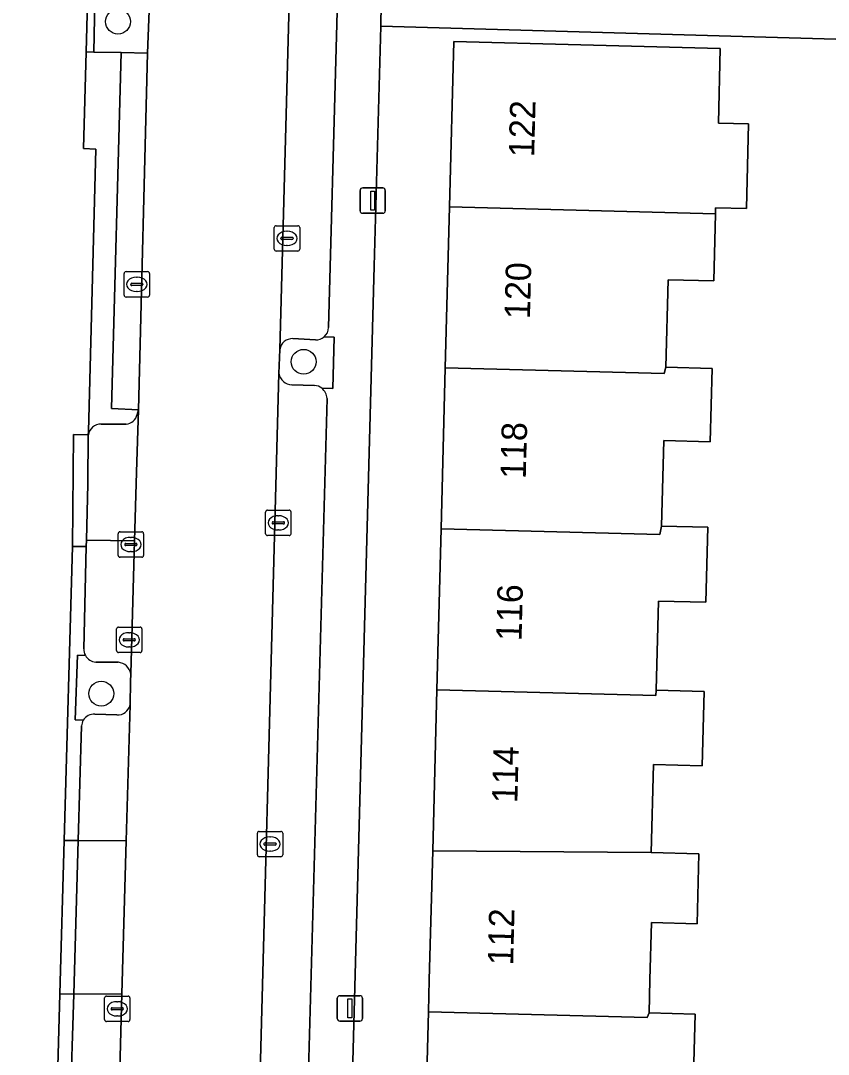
# Model space of a CAD drawing. Extents: x 162082 to 163401, y 388089 to 388636.
# Drawn here: x 162324.72 to 162356.5, y 388247.07 to 388287.72 of the extents above; entities that cross this region are included whole.
import ezdxf

# ---------------------------------------------------------------- set-up
doc = ezdxf.new("R2010")
doc.units = 0
for name, color, linetype in [('IMGEO_Berm_open', 7, 'Continuous'), ('IMGEO_Boom', 7, 'Continuous'), ('IMGEO_Erf', 7, 'Continuous'), ('IMGEO_Fietspad_gesloten', 7, 'Continuous'), ('IMGEO_Groenvoorziening', 7, 'Continuous'), ('IMGEO_Kolk', 7, 'Continuous'), ('IMGEO_Lichtmast', 7, 'Continuous'), ('IMGEO_Pand', 7, 'Continuous'), ('IMGEO_Pand_nummerreeks', 7, 'Continuous'), ('IMGEO_Parkeervlak_open', 7, 'Continuous'), ('IMGEO_Rijbaan_lokaal_gesloten', 7, 'Continuous'), ('IMGEO_Rijbaan_lokaal_open', 7, 'Continuous'), ('IMGEO_Rioolput', 7, 'Continuous'), ('IMGEO_Voetpad_open', 7, 'Continuous')]:
    doc.layers.add(name, color=color, linetype=linetype)

msp = doc.modelspace()

# ---------------------------------------------------------------- linework, layer by layer
at = {"layer": 'IMGEO_Berm_open'}
for points in [[(162327.895, 388289.495), (162328.369, 388307.541), (162327.861, 388307.546), (162327.288, 388286.498), (162327.596, 388286.49), (162327.652, 388289.17), (162327.984, 388289.163)], [(162327.297, 388267.04), (162326.752, 388267.046), (162326.43, 388255.479), (162326.974, 388255.482), (162327.113, 388259.985)], [(162327.198, 388263.017), (162327.297, 388267.04)], [(162327.181, 388260.211), (162326.866, 388260.221), (162326.947, 388262.772), (162327.262, 388262.762)], [(162326.664, 388244.93), (162326.803, 388249.442), (162326.263, 388249.445), (162325.933, 388237.577), (162326.46, 388237.576), (162326.594, 388242.059)]]:
    msp.add_lwpolyline(points, dxfattribs=at)
for centre, radius, start, end in [((162327.726, 388263.014), 0.528, 179.6824, 208.4958), ((162327.598, 388259.962), 0.486, 149.1875, 177.321)]:
    msp.add_arc(centre, radius, start, end, dxfattribs=at)
at = {"layer": 'IMGEO_Boom'}
for centre in [(162328.546, 388287.687), (162335.851, 388274.307), (162327.888, 388261.256)]:
    msp.add_circle(centre, 0.489, dxfattribs=at)
at = {"layer": 'IMGEO_Erf'}
for points in [[(162360.923, 388286.882), (162338.884, 388287.51), (162338.626, 388278.073), (162337.426, 388233.104)], [(162340.599, 388242.417), (162340.764, 388248.748), (162340.797, 388250), (162340.929, 388255.078), (162341.094, 388261.41), (162341.258, 388267.74), (162341.423, 388274.07), (162341.588, 388280.402), (162341.757, 388286.908), (162346.756, 388286.778), (162352.246, 388286.635), (162352.17, 388283.695), (162353.36, 388283.664), (162353.274, 388280.337), (162352.063, 388280.368), (162352.057, 388280.13), (162351.988, 388277.49), (162350.193, 388277.536), (162350.104, 388274.093), (162351.927, 388274.045), (162351.852, 388271.162), (162350.02, 388271.21), (162349.933, 388267.846), (162351.756, 388267.799), (162351.679, 388264.85), (162349.809, 388264.898), (162349.718, 388261.391), (162351.607, 388261.342), (162351.532, 388258.424), (162349.616, 388258.474), (162349.526, 388255.01), (162351.403, 388254.961), (162351.332, 388252.208), (162349.536, 388252.254), (162349.478, 388250), (162349.444, 388248.702), (162351.259, 388248.655), (162351.184, 388245.796)]]:
    msp.add_lwpolyline(points, dxfattribs=at)
at = {"layer": 'IMGEO_Fietspad_gesloten'}
msp.add_lwpolyline([(162324.717, 388195.314), (162324.9, 388201.505), (162325.254, 388213.522), (162325.431, 388219.544), (162325.433, 388219.603), (162325.765, 388231.539), (162325.933, 388237.577), (162326.263, 388249.445), (162326.43, 388255.479), (162326.752, 388267.046), (162326.802, 388271.444), (162327.379, 388271.429), (162327.38, 388271.563), (162327.677, 388282.671), (162327.185, 388282.695), (162327.288, 388286.498), (162327.861, 388307.546), (162327.998, 388312.547), (162328.302, 388323.735), (162328.466, 388329.762)], dxfattribs=at)
at = {"layer": 'IMGEO_Groenvoorziening'}
for points in [[(162327.984, 388289.163), (162327.652, 388289.17), (162327.596, 388286.49), (162328.675, 388286.47), (162329.71, 388286.451), (162329.78, 388288.456), (162329.772, 388288.568)], [(162336.321, 388275.169), (162335.426, 388275.218)], [(162336.565, 388273.265), (162337, 388273.254), (162337.05, 388275.282)], [(162337.05, 388275.282), (162336.658, 388275.292)], [(162334.914, 388274.789), (162334.879, 388273.842)], [(162335.387, 388273.403), (162336.282, 388273.381)], [(162327.262, 388262.762), (162326.947, 388262.772), (162326.866, 388260.221), (162327.181, 388260.211)], [(162328.56, 388262.489), (162327.669, 388262.493)], [(162329.021, 388260.81), (162329.041, 388261.739), (162329.048, 388262.041)], [(162327.635, 388260.446), (162328.502, 388260.419)]]:
    msp.add_lwpolyline(points, dxfattribs=at)
for centre, radius, start, end in [((162335.407, 388274.721), 0.497, 87.7586, 172.16), ((162336.331, 388275.665), 0.497, 268.873, 311.2297), ((162335.414, 388273.948), 0.545, 191.1771, 267.1575), ((162336.224, 388272.835), 0.549, 51.5372, 83.8859), ((162327.723, 388263.017), 0.527, 208.9529, 264.1229), ((162328.512, 388261.947), 0.545, 9.9831, 84.911), ((162327.597, 388259.964), 0.484, 85.4528, 149.2813), ((162328.533, 388260.918), 0.5, 266.4198, 347.5669)]:
    msp.add_arc(centre, radius, start, end, dxfattribs=at)
at = {"layer": 'IMGEO_Kolk'}
for p, q in [((162334.696, 388278.734), (162334.696, 388279.586)), ((162334.771, 388279.66), (162335.623, 388279.66)), ((162335.697, 388279.586), (162335.697, 388278.734)), ((162334.955, 388279.154), (162334.955, 388279.166)), ((162334.998, 388279.203), (162335.396, 388279.203)), ((162335.184, 388279.44), (162335.209, 388279.44)), ((162335.439, 388279.166), (162335.439, 388279.154)), ((162335.393, 388279.117), (162334.995, 388279.117)), ((162335.207, 388278.88), (162335.182, 388278.88)), ((162335.623, 388278.66), (162334.771, 388278.66)), ((162334.353, 388267.548), (162334.353, 388268.4)), ((162334.428, 388268.474), (162335.28, 388268.474)), ((162334.841, 388268.254), (162334.866, 388268.254)), ((162335.354, 388268.4), (162335.354, 388267.548)), ((162334.612, 388267.968), (162334.612, 388267.98)), ((162335.05, 388267.931), (162334.652, 388267.931)), ((162334.655, 388268.017), (162335.053, 388268.017)), ((162335.096, 388267.98), (162335.096, 388267.968)), ((162328.553, 388266.696), (162328.553, 388267.548)), ((162328.628, 388267.622), (162329.48, 388267.622)), ((162329.041, 388267.402), (162329.066, 388267.402)), ((162329.554, 388267.548), (162329.554, 388266.696)), ((162335.28, 388267.474), (162334.428, 388267.474)), ((162334.864, 388267.694), (162334.839, 388267.694)), ((162328.812, 388267.116), (162328.812, 388267.128)), ((162329.25, 388267.079), (162328.852, 388267.079)), ((162328.855, 388267.165), (162329.253, 388267.165)), ((162329.296, 388267.128), (162329.296, 388267.116)), ((162329.48, 388266.622), (162328.628, 388266.622)), ((162329.064, 388266.842), (162329.039, 388266.842)), ((162334.031, 388254.914), (162334.031, 388255.766)), ((162334.106, 388255.84), (162334.958, 388255.84)), ((162334.519, 388255.62), (162334.544, 388255.62)), ((162335.032, 388255.766), (162335.032, 388254.914)), ((162334.29, 388255.334), (162334.29, 388255.346)), ((162334.728, 388255.297), (162334.33, 388255.297)), ((162334.333, 388255.383), (162334.731, 388255.383)), ((162334.774, 388255.346), (162334.774, 388255.334)), ((162334.958, 388254.84), (162334.106, 388254.84)), ((162334.542, 388255.06), (162334.517, 388255.06)), ((162328.016, 388248.435), (162328.016, 388249.287)), ((162328.091, 388249.361), (162328.943, 388249.361)), ((162328.504, 388249.141), (162328.529, 388249.141)), ((162329.017, 388249.287), (162329.017, 388248.435)), ((162328.275, 388248.855), (162328.275, 388248.867)), ((162328.713, 388248.818), (162328.315, 388248.818)), ((162328.318, 388248.904), (162328.716, 388248.904)), ((162328.759, 388248.867), (162328.759, 388248.855)), ((162328.943, 388248.361), (162328.091, 388248.361)), ((162328.527, 388248.581), (162328.502, 388248.581))]:
    msp.add_line(p, q, dxfattribs=at)
for points in [[(162334.696, 388278.734), (162334.696, 388279.586)], [(162334.771, 388279.66), (162335.623, 388279.66)], [(162335.697, 388279.586), (162335.697, 388278.734)], [(162335.623, 388278.66), (162334.771, 388278.66)], [(162334.353, 388267.548), (162334.353, 388268.4)], [(162334.428, 388268.474), (162335.28, 388268.474)], [(162335.354, 388268.4), (162335.354, 388267.548)], [(162328.553, 388266.696), (162328.553, 388267.548)], [(162328.628, 388267.622), (162329.48, 388267.622)], [(162329.554, 388267.548), (162329.554, 388266.696)], [(162335.28, 388267.474), (162334.428, 388267.474)], [(162329.48, 388266.622), (162328.628, 388266.622)], [(162334.031, 388254.914), (162334.031, 388255.766)], [(162334.106, 388255.84), (162334.958, 388255.84)], [(162335.032, 388255.766), (162335.032, 388254.914)], [(162334.958, 388254.84), (162334.106, 388254.84)], [(162328.016, 388248.435), (162328.016, 388249.287)], [(162328.091, 388249.361), (162328.943, 388249.361)], [(162329.017, 388249.287), (162329.017, 388248.435)], [(162328.943, 388248.361), (162328.091, 388248.361)]]:
    msp.add_lwpolyline(points, dxfattribs=at)
for centre, radius, start, end in [((162334.773, 388279.584), 0.0765, 91.552, 178.448), ((162334.773, 388279.584), 0.0765, 91.552, 178.448), ((162335.621, 388279.584), 0.0765, 1.552, 88.448), ((162335.621, 388279.584), 0.0765, 1.552, 88.448), ((162334.995, 388279.163), 0.0403, 85.8775, 175.7526), ((162334.992, 388279.153), 0.0366, 178.938, 274.7102), ((162335.396, 388279.16), 0.043, 264.8664, 352.4533), ((162335.4, 388279.165), 0.0386, 1.7309, 96.639), ((162334.773, 388278.736), 0.0765, 181.552, 268.448), ((162334.773, 388278.736), 0.0765, 181.552, 268.448), ((162335.621, 388278.736), 0.0765, 271.552, 358.448), ((162335.621, 388278.736), 0.0765, 271.552, 358.448), ((162334.43, 388268.398), 0.0765, 91.552, 178.448), ((162334.43, 388268.398), 0.0765, 91.552, 178.448), ((162335.278, 388268.398), 0.0765, 1.552, 88.448), ((162335.278, 388268.398), 0.0765, 1.552, 88.448), ((162334.652, 388267.977), 0.0403, 85.8775, 175.7526), ((162334.649, 388267.967), 0.0366, 178.938, 274.7102), ((162335.053, 388267.974), 0.043, 264.8664, 352.4533), ((162335.057, 388267.979), 0.0386, 1.7309, 96.639), ((162328.63, 388267.546), 0.0765, 91.552, 178.448), ((162328.63, 388267.546), 0.0765, 91.552, 178.448), ((162329.478, 388267.546), 0.0765, 1.552, 88.448), ((162329.478, 388267.546), 0.0765, 1.552, 88.448), ((162334.43, 388267.55), 0.0765, 181.552, 268.448), ((162334.43, 388267.55), 0.0765, 181.552, 268.448), ((162335.278, 388267.55), 0.0765, 271.552, 358.448), ((162335.278, 388267.55), 0.0765, 271.552, 358.448), ((162328.852, 388267.125), 0.0403, 85.8775, 175.7526), ((162328.849, 388267.115), 0.0366, 178.938, 274.7102), ((162329.253, 388267.122), 0.043, 264.8664, 352.4533), ((162329.257, 388267.127), 0.0386, 1.7309, 96.639), ((162328.63, 388266.698), 0.0765, 181.552, 268.448), ((162328.63, 388266.698), 0.0765, 181.552, 268.448), ((162329.478, 388266.698), 0.0765, 271.552, 358.448), ((162329.478, 388266.698), 0.0765, 271.552, 358.448), ((162334.108, 388255.764), 0.0765, 91.552, 178.448), ((162334.108, 388255.764), 0.0765, 91.552, 178.448), ((162334.956, 388255.764), 0.0765, 1.552, 88.448), ((162334.956, 388255.764), 0.0765, 1.552, 88.448), ((162334.33, 388255.343), 0.0403, 85.8775, 175.7526), ((162334.327, 388255.333), 0.0366, 178.938, 274.7102), ((162334.731, 388255.34), 0.043, 264.8664, 352.4533), ((162334.735, 388255.345), 0.0386, 1.7309, 96.639), ((162334.108, 388254.916), 0.0765, 181.552, 268.448), ((162334.108, 388254.916), 0.0765, 181.552, 268.448), ((162334.956, 388254.916), 0.0765, 271.552, 358.448), ((162334.956, 388254.916), 0.0765, 271.552, 358.448), ((162328.093, 388249.285), 0.0765, 91.552, 178.448), ((162328.093, 388249.285), 0.0765, 91.552, 178.448), ((162328.941, 388249.285), 0.0765, 1.552, 88.448), ((162328.941, 388249.285), 0.0765, 1.552, 88.448), ((162328.315, 388248.864), 0.0403, 85.8775, 175.7526), ((162328.312, 388248.854), 0.0366, 178.938, 274.7102), ((162328.716, 388248.861), 0.043, 264.8664, 352.4533), ((162328.72, 388248.866), 0.0386, 1.7309, 96.639), ((162328.093, 388248.437), 0.0765, 181.552, 268.448), ((162328.093, 388248.437), 0.0765, 181.552, 268.448), ((162328.941, 388248.437), 0.0765, 271.552, 358.448), ((162328.941, 388248.437), 0.0765, 271.552, 358.448)]:
    msp.add_arc(centre, radius, start, end, dxfattribs=at)
for centre, major_axis, ratio, start_param, end_param in [((162335.183, 388279.16), (-0.387, 0.002), 0.722429, 4.712389, 7.853982), ((162335.208, 388279.16), (-0.39, 0.002), 0.717154, 1.570796, 4.712389), ((162334.84, 388267.974), (-0.387, 0.002), 0.722429, 4.712389, 7.853982), ((162334.865, 388267.974), (-0.39, 0.002), 0.717154, 1.570796, 4.712389), ((162329.04, 388267.122), (-0.387, 0.002), 0.722429, 4.712389, 7.853982), ((162329.065, 388267.122), (-0.39, 0.002), 0.717154, 1.570796, 4.712389), ((162334.518, 388255.34), (-0.387, 0.002), 0.722429, 4.712389, 7.853982), ((162334.543, 388255.34), (-0.39, 0.002), 0.717154, 1.570796, 4.712389), ((162328.503, 388248.861), (-0.387, 0.002), 0.722429, 4.712389, 7.853982), ((162328.528, 388248.861), (-0.39, 0.002), 0.717154, 1.570796, 4.712389)]:
    msp.add_ellipse(centre, major_axis=major_axis, ratio=ratio, start_param=start_param, end_param=end_param, dxfattribs=at)
at = {"layer": 'IMGEO_Lichtmast'}
for p, q in [((162338.074, 388280.248), (162338.074, 388281.048)), ((162338.074, 388281.048), (162338.074, 388280.248)), ((162338.174, 388281.148), (162338.964, 388281.148)), ((162338.964, 388281.148), (162338.174, 388281.148)), ((162339.064, 388281.048), (162339.064, 388280.248)), ((162339.064, 388280.248), (162339.064, 388281.048)), ((162338.964, 388280.148), (162338.174, 388280.148)), ((162338.174, 388280.148), (162338.964, 388280.148)), ((162337.175, 388248.476), (162337.175, 388249.276)), ((162337.175, 388249.276), (162337.175, 388248.476)), ((162337.275, 388249.376), (162338.065, 388249.376)), ((162338.065, 388249.376), (162337.275, 388249.376)), ((162338.165, 388249.276), (162338.165, 388248.476)), ((162338.165, 388248.476), (162338.165, 388249.276)), ((162338.065, 388248.376), (162337.275, 388248.376)), ((162337.275, 388248.376), (162338.065, 388248.376))]:
    msp.add_line(p, q, dxfattribs=at)
for points in [[(162338.494, 388281.023), (162338.644, 388281.023), (162338.644, 388280.273), (162338.494, 388280.273), (162338.494, 388281.023)], [(162337.595, 388249.251), (162337.745, 388249.251), (162337.745, 388248.501), (162337.595, 388248.501), (162337.595, 388249.251)]]:
    msp.add_lwpolyline(points, dxfattribs=at)
for centre, start, end in [((162338.174, 388281.048), 90, 180), ((162338.174, 388281.048), 90, 180), ((162338.964, 388281.048), 0, 90), ((162338.964, 388281.048), 360, 90), ((162338.174, 388280.248), 180, 270), ((162338.174, 388280.248), 180, 270), ((162338.964, 388280.248), 270, 0), ((162338.964, 388280.248), 270, 0), ((162337.275, 388249.276), 90, 180), ((162337.275, 388249.276), 90, 180), ((162338.065, 388249.276), 0, 90), ((162338.065, 388249.276), 360, 90), ((162337.275, 388248.476), 180, 270), ((162337.275, 388248.476), 180, 270), ((162338.065, 388248.476), 270, 0), ((162338.065, 388248.476), 270, 0)]:
    msp.add_arc(centre, 0.1, start, end, dxfattribs=at)
at = {"layer": 'IMGEO_Pand'}
for points in [[(162341.588, 388280.402), (162352.057, 388280.13), (162352.063, 388280.368), (162353.274, 388280.337), (162353.36, 388283.664), (162352.17, 388283.695), (162352.246, 388286.635), (162346.756, 388286.778), (162341.757, 388286.908)], [(162341.423, 388274.07), (162350.033, 388273.847), (162350.104, 388274.093), (162350.193, 388277.536), (162351.988, 388277.49), (162352.057, 388280.13), (162341.588, 388280.402)], [(162341.423, 388274.07), (162341.258, 388267.74), (162349.868, 388267.517), (162349.933, 388267.846), (162350.02, 388271.21), (162351.852, 388271.162), (162351.927, 388274.045), (162350.104, 388274.093), (162350.033, 388273.847)], [(162349.718, 388261.391), (162349.809, 388264.898), (162351.679, 388264.85), (162351.756, 388267.799), (162349.933, 388267.846), (162349.868, 388267.517), (162341.258, 388267.74), (162341.094, 388261.41), (162349.704, 388261.187)], [(162349.718, 388261.391), (162349.704, 388261.187), (162341.094, 388261.41), (162340.929, 388255.078), (162349.526, 388255.01), (162349.616, 388258.474), (162351.532, 388258.424), (162351.607, 388261.342)], [(162349.444, 388248.702), (162349.478, 388250), (162349.536, 388252.254), (162351.332, 388252.208), (162351.403, 388254.961), (162349.526, 388255.01), (162340.929, 388255.078), (162340.797, 388250), (162340.764, 388248.748), (162349.373, 388248.524)], [(162340.599, 388242.417), (162349.209, 388242.193), (162349.267, 388242.371), (162349.358, 388245.844), (162351.184, 388245.796), (162351.259, 388248.655), (162349.444, 388248.702), (162349.373, 388248.524), (162340.764, 388248.748)]]:
    msp.add_lwpolyline(points, close=True, dxfattribs=at)
at = {"layer": 'IMGEO_Parkeervlak_open'}
for points in [[(162335.561, 388298.654), (162334.914, 388274.789)], [(162336.831, 388275.651), (162337.429, 388297.641)], [(162335.426, 388275.218), (162336.321, 388275.169)], [(162334.879, 388273.842), (162333.941, 388238.998)], [(162336.282, 388273.381), (162335.387, 388273.403)], [(162335.858, 388239.827), (162336.775, 388272.868)], [(162329.198, 388267.26), (162327.303, 388267.291), (162327.297, 388267.04), (162327.198, 388263.017)], [(162329.048, 388262.041), (162329.198, 388267.26)], [(162327.669, 388262.493), (162328.56, 388262.489)], [(162327.113, 388259.985), (162326.974, 388255.482), (162328.872, 388255.468), (162329.021, 388260.81)], [(162328.502, 388260.419), (162327.635, 388260.446)], [(162328.704, 388249.449), (162326.803, 388249.442), (162326.664, 388244.93)], [(162328.552, 388243.983), (162328.704, 388249.449)]]:
    msp.add_lwpolyline(points, dxfattribs=at)
for centre, radius, start, end in [((162336.366, 388275.654), 0.465, 308.897, 359.6447), ((162335.407, 388274.721), 0.497, 87.7586, 172.16), ((162336.331, 388275.665), 0.497, 268.873, 311.2297), ((162335.414, 388273.948), 0.545, 191.1771, 267.1575), ((162336.224, 388272.835), 0.549, 51.5372, 83.8859), ((162336.22, 388272.829), 0.556, 4.0585, 51.6962), ((162327.726, 388263.014), 0.528, 179.6824, 208.4958), ((162327.723, 388263.017), 0.527, 208.9529, 264.1229), ((162328.512, 388261.947), 0.545, 9.9831, 84.911), ((162327.597, 388259.964), 0.484, 85.4528, 149.2813), ((162328.533, 388260.918), 0.5, 266.4198, 347.5669), ((162327.598, 388259.962), 0.486, 149.1875, 177.321)]:
    msp.add_arc(centre, radius, start, end, dxfattribs=at)
at = {"layer": 'IMGEO_Rijbaan_lokaal_gesloten'}
for points in [[(162333.941, 388238.998), (162334.879, 388273.842), (162334.914, 388274.789), (162335.561, 388298.654), (162335.603, 388299.877), (162336.258, 388323.727), (162336.315, 388326.293), (162336.353, 388327.986), (162337.184, 388357.359)], [(162330.881, 388329.508), (162330.725, 388323.684), (162330.58, 388318.269), (162330.569, 388317.993), (162330.545, 388317.428), (162330.4, 388312.003), (162330.292, 388307.974), (162329.772, 388288.568), (162329.78, 388288.456), (162329.71, 388286.451), (162329.348, 388272.419), (162329.276, 388269.966), (162329.198, 388267.26), (162329.048, 388262.041), (162329.041, 388261.739), (162329.021, 388260.81), (162328.872, 388255.468), (162328.704, 388249.449), (162328.552, 388243.983)]]:
    msp.add_lwpolyline(points, dxfattribs=at)
at = {"layer": 'IMGEO_Rijbaan_lokaal_open'}
for points in [[(162329.276, 388269.966), (162329.348, 388272.419), (162329.299, 388272.239)], [(162328.866, 388271.851), (162327.881, 388271.855)], [(162327.379, 388271.429), (162327.359, 388269.532), (162327.358, 388269.504), (162327.303, 388267.291), (162329.198, 388267.26), (162329.276, 388269.966)]]:
    msp.add_lwpolyline(points, dxfattribs=at)
for points in [[(162327.358, 388269.504), (162327.359, 388269.532), (162327.379, 388271.429), (162326.802, 388271.444), (162326.752, 388267.046), (162327.297, 388267.04), (162327.303, 388267.291)], [(162326.974, 388255.482), (162326.43, 388255.479), (162326.263, 388249.445), (162326.803, 388249.442)], [(162328.872, 388255.468), (162326.974, 388255.482), (162326.803, 388249.442), (162328.704, 388249.449)]]:
    msp.add_lwpolyline(points, close=True, dxfattribs=at)
for centre, radius, start, end in [((162328.819, 388272.339), 0.49, 275.4583, 348.267), ((162327.862, 388271.369), 0.486, 87.7081, 172.9281)]:
    msp.add_arc(centre, radius, start, end, dxfattribs=at)
at = {"layer": 'IMGEO_Rioolput'}
for p, q in [((162328.787, 388276.928), (162328.787, 388277.78)), ((162328.862, 388277.854), (162329.714, 388277.854)), ((162329.275, 388277.634), (162329.3, 388277.634)), ((162329.788, 388277.78), (162329.788, 388276.928)), ((162329.046, 388277.348), (162329.046, 388277.36)), ((162329.484, 388277.311), (162329.086, 388277.311)), ((162329.089, 388277.397), (162329.487, 388277.397)), ((162329.53, 388277.36), (162329.53, 388277.348)), ((162329.714, 388276.854), (162328.862, 388276.854)), ((162329.298, 388277.074), (162329.273, 388277.074)), ((162328.488, 388262.947), (162328.488, 388263.799)), ((162328.563, 388263.873), (162329.415, 388263.873)), ((162329.489, 388263.799), (162329.489, 388262.947)), ((162328.747, 388263.367), (162328.747, 388263.379)), ((162329.185, 388263.33), (162328.787, 388263.33)), ((162328.79, 388263.416), (162329.188, 388263.416)), ((162328.976, 388263.653), (162329.001, 388263.653)), ((162329.231, 388263.379), (162329.231, 388263.367)), ((162329.415, 388262.873), (162328.563, 388262.873)), ((162328.999, 388263.093), (162328.974, 388263.093))]:
    msp.add_line(p, q, dxfattribs=at)
for points in [[(162328.787, 388276.928), (162328.787, 388277.78)], [(162328.862, 388277.854), (162329.714, 388277.854)], [(162329.788, 388277.78), (162329.788, 388276.928)], [(162329.714, 388276.854), (162328.862, 388276.854)], [(162328.488, 388262.947), (162328.488, 388263.799)], [(162328.563, 388263.873), (162329.415, 388263.873)], [(162329.489, 388263.799), (162329.489, 388262.947)], [(162329.415, 388262.873), (162328.563, 388262.873)]]:
    msp.add_lwpolyline(points, dxfattribs=at)
for centre, radius, start, end in [((162328.864, 388277.778), 0.0765, 91.552, 178.448), ((162328.864, 388277.778), 0.0765, 91.552, 178.448), ((162329.712, 388277.778), 0.0765, 1.552, 88.448), ((162329.712, 388277.778), 0.0765, 1.552, 88.448), ((162329.086, 388277.357), 0.0403, 85.8775, 175.7526), ((162329.083, 388277.347), 0.0366, 178.938, 274.7102), ((162329.487, 388277.354), 0.043, 264.8664, 352.4533), ((162329.491, 388277.359), 0.0386, 1.7309, 96.639), ((162328.864, 388276.93), 0.0765, 181.552, 268.448), ((162328.864, 388276.93), 0.0765, 181.552, 268.448), ((162329.712, 388276.93), 0.0765, 271.552, 358.448), ((162329.712, 388276.93), 0.0765, 271.552, 358.448), ((162328.565, 388263.797), 0.0765, 91.552, 178.448), ((162328.565, 388263.797), 0.0765, 91.552, 178.448), ((162329.413, 388263.797), 0.0765, 1.552, 88.448), ((162329.413, 388263.797), 0.0765, 1.552, 88.448), ((162328.787, 388263.376), 0.0403, 85.8775, 175.7526), ((162328.784, 388263.366), 0.0366, 178.938, 274.7102), ((162329.188, 388263.373), 0.043, 264.8664, 352.4533), ((162329.192, 388263.378), 0.0386, 1.7309, 96.639), ((162328.565, 388262.949), 0.0765, 181.552, 268.448), ((162328.565, 388262.949), 0.0765, 181.552, 268.448), ((162329.413, 388262.949), 0.0765, 271.552, 358.448), ((162329.413, 388262.949), 0.0765, 271.552, 358.448)]:
    msp.add_arc(centre, radius, start, end, dxfattribs=at)
for centre, major_axis, ratio, start_param, end_param in [((162329.274, 388277.354), (-0.387, 0.002), 0.722429, 4.712389, 7.853982), ((162329.299, 388277.354), (-0.39, 0.002), 0.717154, 1.570796, 4.712389), ((162328.975, 388263.373), (-0.387, 0.002), 0.722429, 4.712389, 7.853982), ((162329, 388263.373), (-0.39, 0.002), 0.717154, 1.570796, 4.712389)]:
    msp.add_ellipse(centre, major_axis=major_axis, ratio=ratio, start_param=start_param, end_param=end_param, dxfattribs=at)
at = {"layer": 'IMGEO_Voetpad_open'}
for points in [[(162333.482, 388208.465), (162336.785, 388208.588), (162337.396, 388230.092), (162337.426, 388233.104), (162338.626, 388278.073), (162338.884, 388287.51), (162338.908, 388288.392), (162339.857, 388323.155), (162340.01, 388328.125), (162341.629, 388387.219), (162341.671, 388388.741), (162343.386, 388452.443)], [(162337.429, 388297.641), (162336.831, 388275.651)], [(162338.908, 388288.392), (162338.884, 388287.51), (162360.923, 388286.882)], [(162328.675, 388286.47), (162327.596, 388286.49), (162327.288, 388286.498), (162327.185, 388282.695), (162327.677, 388282.671), (162327.38, 388271.563), (162327.379, 388271.429)], [(162329.299, 388272.239), (162329.348, 388272.419), (162328.287, 388272.466), (162328.675, 388286.47)], [(162336.658, 388275.292), (162337.05, 388275.282), (162337, 388273.254), (162336.565, 388273.265)], [(162336.775, 388272.868), (162335.858, 388239.827)], [(162327.881, 388271.855), (162328.866, 388271.851)]]:
    msp.add_lwpolyline(points, dxfattribs=at)
msp.add_lwpolyline([(162329.71, 388286.451), (162328.675, 388286.47), (162328.287, 388272.466), (162329.348, 388272.419)], close=True, dxfattribs=at)
for centre, radius, start, end in [((162336.366, 388275.654), 0.465, 308.897, 359.6447), ((162336.22, 388272.829), 0.556, 4.0585, 51.6962), ((162328.819, 388272.339), 0.49, 275.4583, 348.267), ((162327.862, 388271.369), 0.486, 87.7081, 172.9281)]:
    msp.add_arc(centre, radius, start, end, dxfattribs=at)

# ---------------------------------------------------------------- texts
at = {"layer": 'IMGEO_Pand_nummerreeks'}
for s, p in [('122', (162344.92, 388282.346)), ('120', (162344.754, 388275.978)), ('118', (162344.59, 388269.693)), ('116', (162344.424, 388263.317)), ('114', (162344.259, 388256.942)), ('112', (162344.093, 388250.564))]:
    msp.add_text(s, height=1, rotation=88.5094, dxfattribs=at).set_placement(p)

doc.saveas('drawing.dxf')
